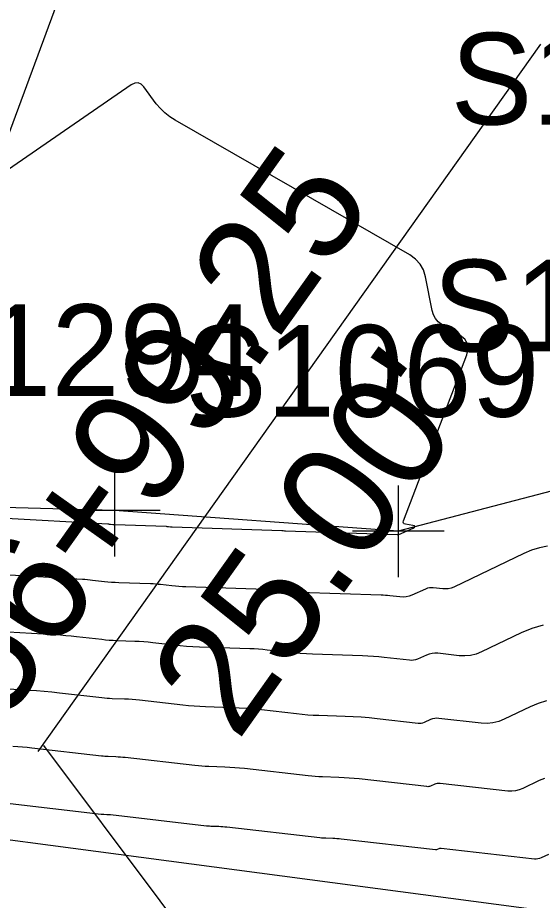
# Model space of a CAD drawing. Extents: x 816928 to 825690, y 436959 to 448212.
# Drawn here: x 818922.82 to 818945.7, y 445191.59 to 445230.11 of the extents above; entities that cross this region are included whole.
import ezdxf

# ---------------------------------------------------------------- set-up
doc = ezdxf.new("R2010")
doc.units = 0
for name, color, linetype in [('SURVEY - CONTOURS - Index with Text', 7, 'Continuous'), ('SURVEY - CONTOURS - Intermediate with optional Text', 7, 'Continuous'), ('SURVEY - DRAINAGE - Bridge Hydraulic Data - Points - Locators', 7, 'Continuous'), ('SURVEY - DRAINAGE - Bridge Hydraulic Data - Points - Numbers', 7, 'Continuous'), ('SURVEY - DRAINAGE - Bridge Hydraulic Data with Text', 7, 'Continuous'), ('SURVEY - DTM - Breaklines', 7, 'Continuous'), ('SURVEY - DTM - Breaklines - Points - Locators', 7, 'Continuous'), ('SURVEY - DTM - Breaklines - Points - Numbers', 7, 'Continuous'), ('SURVEY - PROPERTY - Station and Offset Flags', 7, 'Continuous'), ('SURVEY - VEGETATION - Features with Text', 7, 'Continuous')]:
    doc.layers.add(name, color=color, linetype=linetype)

msp = doc.modelspace()

# ---------------------------------------------------------------- linework, layer by layer
at = {"layer": 'SURVEY - CONTOURS - Index with Text'}
for points in [[(818939.446, 445207.554), (818940.065, 445207.83), (818940.132, 445207.868), (818940.152, 445207.899), (818940.125, 445207.925), (818940.051, 445207.945), (818939.734, 445208.002), (818939.678, 445208.02), (818939.645, 445208.052), (818939.635, 445208.097), (818939.648, 445208.155), (818942.414, 445215.398), (818942.473, 445215.652), (818942.445, 445215.876), (818942.329, 445216.071), (818942.127, 445216.235), (818941.323, 445216.724), (818941.168, 445216.841), (818941.045, 445216.98), (818940.956, 445217.143), (818940.9, 445217.329), (818940.605, 445218.802), (818940.515, 445219.098), (818940.371, 445219.356), (818940.173, 445219.574), (818939.921, 445219.754), (818929.683, 445225.631), (818929.451, 445225.78), (818929.238, 445225.951), (818929.044, 445226.143), (818928.868, 445226.356), (818928.327, 445227.087), (818928.206, 445227.21), (818928.073, 445227.266), (818927.929, 445227.256), (818927.774, 445227.178), (818917.013, 445219.754)], [(818922.058, 445208.285), (818926.751, 445208.015), (818926.781, 445208.013), (818926.812, 445208.011), (818926.842, 445208.008), (818926.873, 445208.004), (818926.972, 445207.993), (818926.994, 445207.991), (818927.015, 445207.989), (818927.037, 445207.988), (818927.058, 445207.987), (818929.295, 445207.91), (818929.321, 445207.909), (818929.347, 445207.907), (818929.373, 445207.905), (818929.399, 445207.902), (818929.483, 445207.892), (818929.501, 445207.89), (818929.519, 445207.889), (818929.537, 445207.888), (818929.555, 445207.887), (818934.336, 445207.727), (818934.353, 445207.727), (818934.369, 445207.726), (818934.386, 445207.724), (818934.402, 445207.723), (818934.455, 445207.716), (818934.467, 445207.715), (818934.478, 445207.714), (818934.49, 445207.714), (818934.501, 445207.713), (818939.379, 445207.556), (818939.386, 445207.555), (818939.393, 445207.555), (818939.399, 445207.554), (818939.406, 445207.554), (818939.428, 445207.551), (818939.433, 445207.551), (818939.437, 445207.551), (818939.442, 445207.552), (818939.446, 445207.554)], [(818945.969, 445193.588), (818945.651, 445193.436), (818945.583, 445193.408), (818945.512, 445193.391), (818945.44, 445193.384), (818945.366, 445193.388), (818941.29, 445193.849), (818941.264, 445193.85), (818941.239, 445193.848), (818941.214, 445193.842), (818941.19, 445193.833), (818941.112, 445193.799), (818941.095, 445193.792), (818941.078, 445193.788), (818941.06, 445193.787), (818941.042, 445193.788), (818936.932, 445194.256), (818936.84, 445194.266), (818936.747, 445194.273), (818936.655, 445194.279), (818936.563, 445194.283), (818936.261, 445194.293), (818936.196, 445194.296), (818936.132, 445194.3), (818936.067, 445194.305), (818936.003, 445194.312), (818931.942, 445194.776), (818931.855, 445194.786), (818931.767, 445194.793), (818931.68, 445194.798), (818931.593, 445194.802), (818931.307, 445194.812), (818931.246, 445194.814), (818931.185, 445194.818), (818931.124, 445194.823), (818931.063, 445194.83), (818926.868, 445195.312), (818926.828, 445195.316), (818926.788, 445195.319), (818926.748, 445195.322), (818926.708, 445195.324), (818926.577, 445195.328), (818926.548, 445195.329), (818926.52, 445195.331), (818926.492, 445195.334), (818926.464, 445195.337), (818922.239, 445195.823)]]:
    msp.add_lwpolyline(points, dxfattribs=at)
at = {"layer": 'SURVEY - CONTOURS - Intermediate with optional Text'}
for points in [[(818945.933, 445207.037), (818945.578, 445206.97), (818945.233, 445206.867), (818944.896, 445206.726), (818941.838, 445205.261), (818941.723, 445205.215), (818941.604, 445205.186), (818941.483, 445205.175), (818941.359, 445205.18), (818940.948, 445205.227), (818940.861, 445205.231), (818940.776, 445205.223), (818940.693, 445205.205), (818940.611, 445205.174), (818940.014, 445204.908), (818939.889, 445204.861), (818939.76, 445204.832), (818939.629, 445204.821), (818939.495, 445204.828), (818939.053, 445204.878), (818938.958, 445204.888), (818938.863, 445204.896), (818938.768, 445204.902), (818938.673, 445204.906), (818935.098, 445205.021), (818934.954, 445205.027), (818934.809, 445205.036), (818934.665, 445205.048), (818934.521, 445205.063), (818934.051, 445205.117), (818933.95, 445205.128), (818933.849, 445205.136), (818933.747, 445205.143), (818933.646, 445205.147), (818930.159, 445205.263), (818930.006, 445205.27), (818929.853, 445205.28), (818929.7, 445205.293), (818929.547, 445205.309), (818929.049, 445205.366), (818928.942, 445205.377), (818928.835, 445205.386), (818928.728, 445205.393), (818928.621, 445205.398), (818927.233, 445205.446), (818927.075, 445205.453), (818926.917, 445205.463), (818926.759, 445205.476), (818926.601, 445205.493), (818926.087, 445205.552), (818925.976, 445205.564), (818925.866, 445205.574), (818925.755, 445205.583), (818925.644, 445205.59), (818922.238, 445205.786)], [(818945.736, 445203.599), (818945.249, 445203.453), (818944.774, 445203.255), (818943.049, 445202.428), (818942.815, 445202.335), (818942.575, 445202.276), (818942.329, 445202.253), (818942.077, 445202.264), (818941.148, 445202.369), (818941.02, 445202.375), (818940.894, 445202.365), (818940.771, 445202.337), (818940.65, 445202.292), (818940.261, 445202.118), (818940.176, 445202.087), (818940.09, 445202.067), (818940.002, 445202.06), (818939.912, 445202.064), (818938.808, 445202.19), (818938.571, 445202.215), (818938.334, 445202.234), (818938.096, 445202.249), (818937.859, 445202.259), (818935.686, 445202.329), (818935.413, 445202.341), (818935.14, 445202.358), (818934.868, 445202.381), (818934.596, 445202.409), (818933.709, 445202.511), (818933.519, 445202.531), (818933.328, 445202.547), (818933.137, 445202.559), (818932.946, 445202.567), (818930.747, 445202.64), (818930.466, 445202.653), (818930.186, 445202.671), (818929.906, 445202.694), (818929.627, 445202.723), (818928.715, 445202.828), (818928.519, 445202.849), (818928.323, 445202.865), (818928.127, 445202.878), (818927.93, 445202.887), (818927.151, 445202.913), (818926.984, 445202.921), (818926.818, 445202.932), (818926.651, 445202.946), (818926.485, 445202.963), (818925.39, 445203.089), (818925.155, 445203.115), (818924.919, 445203.137), (818924.684, 445203.155), (818924.448, 445203.17), (818922.404, 445203.288)], [(818945.88, 445200.286), (818945.521, 445200.178), (818945.172, 445200.032), (818944.046, 445199.493), (818943.801, 445199.395), (818943.551, 445199.334), (818943.294, 445199.309), (818943.031, 445199.321), (818941.195, 445199.529), (818941.101, 445199.534), (818941.009, 445199.526), (818940.919, 445199.505), (818940.83, 445199.472), (818940.545, 445199.345), (818940.483, 445199.322), (818940.419, 445199.308), (818940.355, 445199.302), (818940.289, 445199.305), (818938.502, 445199.509), (818938.154, 445199.545), (818937.805, 445199.574), (818937.455, 445199.596), (818937.105, 445199.611), (818935.961, 445199.648), (818935.716, 445199.658), (818935.471, 445199.674), (818935.227, 445199.694), (818934.983, 445199.72), (818933.461, 445199.894), (818933.134, 445199.928), (818932.807, 445199.955), (818932.48, 445199.976), (818932.152, 445199.99), (818931.009, 445200.028), (818930.764, 445200.039), (818930.519, 445200.055), (818930.275, 445200.075), (818930.031, 445200.101), (818928.138, 445200.318), (818927.975, 445200.335), (818927.811, 445200.349), (818927.648, 445200.36), (818927.484, 445200.367), (818926.948, 445200.385), (818926.833, 445200.391), (818926.719, 445200.398), (818926.604, 445200.408), (818926.49, 445200.42), (818924.64, 445200.633), (818924.307, 445200.669), (818923.973, 445200.7), (818923.639, 445200.726), (818923.305, 445200.748), (818922.213, 445200.811)], [(818945.794, 445196.904), (818945.57, 445196.81), (818944.849, 445196.464), (818944.692, 445196.402), (818944.531, 445196.363), (818944.367, 445196.347), (818944.198, 445196.354), (818941.243, 445196.689), (818941.183, 445196.692), (818941.124, 445196.687), (818941.066, 445196.674), (818941.01, 445196.653), (818940.828, 445196.572), (818940.789, 445196.557), (818940.749, 445196.548), (818940.708, 445196.544), (818940.666, 445196.547), (818937.717, 445196.883), (818937.497, 445196.905), (818937.276, 445196.924), (818937.055, 445196.938), (818936.834, 445196.947), (818936.111, 445196.97), (818935.956, 445196.977), (818935.801, 445196.987), (818935.647, 445197), (818935.493, 445197.016), (818932.716, 445197.333), (818932.502, 445197.356), (818932.287, 445197.374), (818932.072, 445197.387), (818931.857, 445197.397), (818931.153, 445197.42), (818931.003, 445197.427), (818930.852, 445197.436), (818930.702, 445197.449), (818930.552, 445197.465), (818927.503, 445197.815), (818927.402, 445197.826), (818927.3, 445197.834), (818927.198, 445197.841), (818927.096, 445197.845), (818926.762, 445197.857), (818926.691, 445197.86), (818926.619, 445197.865), (818926.548, 445197.871), (818926.477, 445197.878), (818923.439, 445198.228), (818923.234, 445198.25), (818923.028, 445198.269), (818922.821, 445198.286), (818922.615, 445198.299)]]:
    msp.add_lwpolyline(points, dxfattribs=at)
at = {"layer": 'SURVEY - DRAINAGE - Bridge Hydraulic Data - Points - Locators'}
for p, q in [((818927.039, 445210.595), (818927.039, 445206.595)), ((818929.039, 445208.595), (818925.039, 445208.595))]:
    msp.add_line(p, q, dxfattribs=at)
at = {"layer": 'SURVEY - DRAINAGE - Bridge Hydraulic Data with Text'}
for points in [[(818939.42, 445207.694), (818927.039, 445208.595), (818909.794, 445209.059), (818907.155, 445223.401), (818913.895, 445264.677), (818910.077, 445263.438), (818900.097, 445237.451), (818897.164, 445208.339), (818868.22, 445203.878)], [(818981.856, 445170.386), (818981.679, 445172.324), (818961.15, 445189.092), (818885.148, 445199.156), (818830.646, 445194.716), (818800.042, 445220.122), (818756.964, 445204.922), (818710.566, 445206.148)]]:
    msp.add_lwpolyline(points, dxfattribs=at)
at = {"layer": 'SURVEY - DTM - Breaklines'}
msp.add_lwpolyline([(819073.298, 445355.122), (819048.115, 445322.006), (819023.42, 445284.723), (818992.563, 445243.615), (818984.238, 445238.804), (818960.537, 445218.165), (818958.862, 445226.04), (818957.684, 445235.166), (818941.199, 445267.453), (818950.993, 445220.447), (818950.259, 445210.542), (818939.42, 445207.694)], dxfattribs=at)
at = {"layer": 'SURVEY - DTM - Breaklines - Points - Locators'}
for p, q in [((818939.42, 445209.694), (818939.42, 445205.694)), ((818941.42, 445207.694), (818937.42, 445207.694))]:
    msp.add_line(p, q, dxfattribs=at)
at = {"layer": 'SURVEY - PROPERTY - Station and Offset Flags'}
msp.add_line((818945.629, 445228.948), (818923.696, 445198.087), dxfattribs=at)
msp.add_lwpolyline([(818923.948, 445198.34), (818939.168, 445178.006)], dxfattribs=at)
at = {"layer": 'SURVEY - VEGETATION - Features with Text'}
msp.add_lwpolyline([(818921.649, 445531.075), (818911.357, 445419.447), (818895.02, 445347.602), (818900.539, 445320.739), (818919.801, 445285.725), (818871.556, 445256.506), (818910.143, 445268.505), (818928.958, 445242.751), (818875.35, 445097.529)], dxfattribs=at)

# ---------------------------------------------------------------- texts
at = {"layer": 'SURVEY - DRAINAGE - Bridge Hydraulic Data - Points - Numbers'}
msp.add_text('S1294', height=4, dxfattribs=at).set_placement((818917.751, 445213.595))
at = {"layer": 'SURVEY - DTM - Breaklines - Points - Numbers'}
for s, p in [('S1067', (818941.705, 445225.447)), ('S1068', (818940.924, 445215.542)), ('S1069', (818930.117, 445212.694))]:
    msp.add_text(s, height=4, dxfattribs=at).set_placement(p)
at = {"layer": 'SURVEY - PROPERTY - Station and Offset Flags'}
for s, p in [('56+99.25', (818922.168, 445199.174)), ("25.00'", (818932.401, 445198.468))]:
    msp.add_text(s, height=5, rotation=54.5985, dxfattribs=at).set_placement(p)

doc.saveas('drawing.dxf')
